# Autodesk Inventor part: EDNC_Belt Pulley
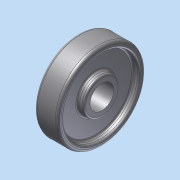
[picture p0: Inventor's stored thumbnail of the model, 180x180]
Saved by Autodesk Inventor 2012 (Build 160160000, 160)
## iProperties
Created: 2010-10
Part Number: EDNC_Belt Pulley
Document SubType Name: Modeling
Designer: JSSONG
Density: 1 g/cm^3
Mass: 103.845 g
Surface Area: 246.927 cm^2
Volume: 103.845 cm^3
Material: 기본값
Author: JSSONG
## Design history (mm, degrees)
sketch "스케치1"
  geometry: L1 (0, 0)-(12.5, 0); L2 (12.5, 0)-(12.5, 46); L3 (12.5, 46)-(-12.5, 46); L4 (-12.5, 46)-(-12.5, 0); L5 (-12.5, 0)-(0, 0); L6 (-12.5, 46)-(12.5, 46); L7 (12.5, 39.5)-(6, 39.5); L8 (6, 39.5)-(6, 19); L9 (6, 19)-(12.5, 19); L10 (12.5, 12.5)-(-12.5, 12.5); L11 (-12.5, 12.5)-(-12.5, 19); L12 (-12.5, 19)-(-6, 19); L13 (-6, 19)-(-6, 39.5); L14 (-6, 39.5)-(-12.5, 39.5); L15 (-12.5, 39.5)-(-12.5, 46); L16 (12.5, 39.5)-(12.5, 46); L17 (12.5, 19)-(12.5, 12.5)
  constraints: 34 end point, 9 collinear, 6 perpendicular, 6 point on line, 4 parallel, 1 horizontal
  dimensions: "d0" = 92 diameter of L3 L1; "d1" = 25 distance of L2.end L3.end; "d2" = 25 diameter of L10 L1; "d3" = 20.5 distance of L12.end L13.end; "d4" = 6.5 distance between parallel lines of L10 L12; "d5" = 38 diameter of L9 L1 (derived); "d6" = 12 distance between parallel lines of L13 L8
revolve "회전1" sketch "스케치1" stored, may be unused: angle "d7" = 90 deg
fillet "모깎기1" dims "d8" = 3, "d9" = 2
node "솔리드1"
